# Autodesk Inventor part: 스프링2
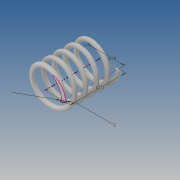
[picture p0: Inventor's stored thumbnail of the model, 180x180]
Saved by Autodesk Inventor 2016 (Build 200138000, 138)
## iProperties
Created: 2016-10
Part Number: 스프링2
Material: Generic
Document SubType Name: Modeling
Designer: Administrator
Density: 1 g/cm^3
Appearance: Default
Mass: 0.874294 g
Surface Area: 17.7466 cm^2
Volume: 0.874294 cm^3
Author: Administrator
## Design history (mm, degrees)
sketch "스케치1"
  geometry: L1 (0, 0)-(-9, 0); L2 (-9, 0)-(-9, -27); L3 (-9, -27)-(0, -27); L4 (0, -27)-(0, 0); C1 r 1 at (-9, 0)
  constraints: 8 end point, 2 parallel, 1 centre point, 1 coincident, 1 horizontal, 1 perpendicular
  dimensions: "d0" = 2 diameter of C1; "d1" = 27 distance of L1.end L2.end (derived); "d2" = 18 diameter of L2 L4
feature "코일1" pitch "d3" = 10; turns "d5" = 5; dims "d4" = 27 (= d1), "d6" = 0, angle "d7" = 90 deg, angle "d8" = 90 deg, "d9" = 0, "d10" = 0
sketch "스케치2"
  geometry: L1 (10, 0)-(8, 0) reference; 1 further point
  constraints: 1 horizontal alignment
  node "절단 모서리 투영1"
extrude "돌출1" cut sketch "스케치2" stored distance "d11" = 10; taper "d12" = 0 deg
node "작업 평면3"
sketch "스케치3"
  geometry: L1 (-1, 0)-(1, 0) reference; 1 further point
  constraints: 1 horizontal alignment
extrude "돌출2" cut sketch "스케치3" stored distance "d14" = 0; taper "d15" = 0 deg
node "솔리드1"
node "절단 모서리 투영2"
other parameters: "d13" = 90 deg
